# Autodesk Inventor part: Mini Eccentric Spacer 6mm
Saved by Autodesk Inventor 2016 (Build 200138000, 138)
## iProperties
Created: 2015-11
Part Number: Mini Eccentric Spacer 6mm
Material: Generic
Document SubType Name: Modeling
Designer: John
Density: 1 g/cm^3
Appearance: Default
Author: John
Revision Number: ANY
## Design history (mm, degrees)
feature "Cut-Revolve1"
body "Solid1"
